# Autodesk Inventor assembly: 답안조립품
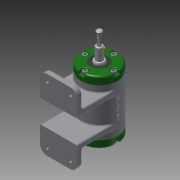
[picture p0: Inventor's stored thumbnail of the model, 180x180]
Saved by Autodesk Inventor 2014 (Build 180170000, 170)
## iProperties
Created: 2017-02
Part Number: 답안조립품
Document SubType Name: Assembly
Designer: owner
Author: owner
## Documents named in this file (9)
- C:\Users\owner\Desktop\470207V1005\답안조립품.iam
- C:\Users\owner\Desktop\470207V1005\본체.ipt
- C:\Users\owner\Desktop\470207V1005\베어링 15 x 32 x 9.ipt
- C:\Users\owner\Desktop\470207V1005\축.ipt
- C:\Users\owner\Desktop\470207V1005\뒤커버.ipt
- C:\Users\owner\Desktop\470207V1005\볼트 M4 x 12.ipt
- C:\Users\owner\Desktop\470207V1005\앞커버.ipt
- C:\Users\owner\Desktop\470207V1005\오일 실 15 25 7.ipt
- C:\Users\owner\Desktop\470207V1005\키 3 x 3 x 12.ipt
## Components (10 placed, 2 different names)
1. KS B 2023 6002 - 15 x 32 x 9:1
2. KS B 2023 6002 - 15 x 32 x 9:2
3. ISO 4762 M4 x 12:1
4. ISO 4762 M4 x 12:2
5. ISO 4762 M4 x 12:3
6. ISO 4762 M4 x 12:4
7. ISO 4762 M4 x 12:5
8. ISO 4762 M4 x 12:6
9. ISO 4762 M4 x 12:7
10. ISO 4762 M4 x 12:8
